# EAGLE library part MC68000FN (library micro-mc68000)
68xxx PROCESSOR
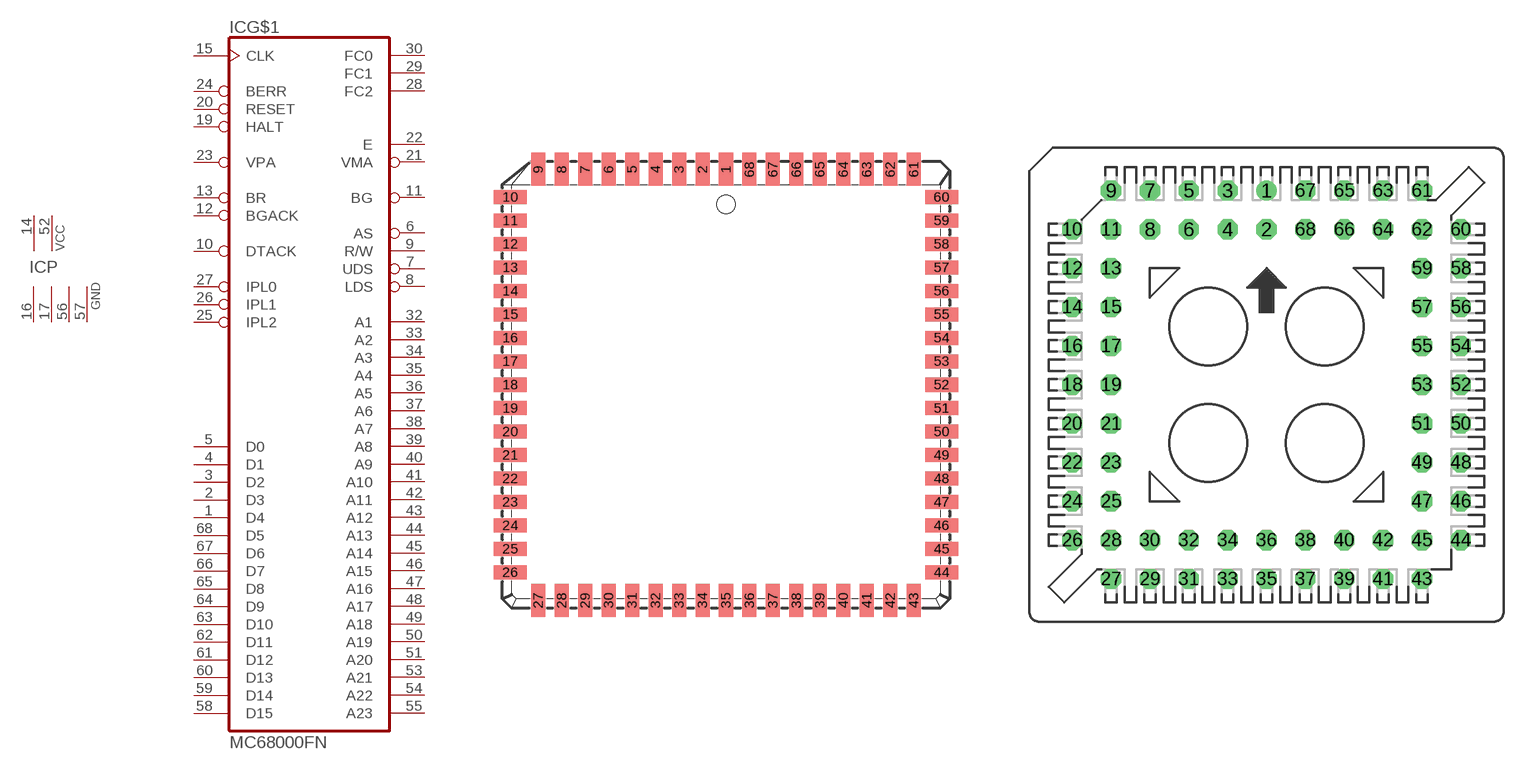
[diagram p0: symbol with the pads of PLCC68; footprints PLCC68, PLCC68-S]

Designator prefix IC; gates G$1=68000 P=2PWR4GND

## MC68000FN (MF: MOTOROLA; MPN: MC68HC000FN20; OC_FARNELL: unknown; OC_NEWARK: 66F833)  [PLCC68]
1  G$1:D4
2  G$1:D3
3  G$1:D2
4  G$1:D1
5  G$1:D0
6  G$1:AS  out
7  G$1:UDS  out
8  G$1:LDS  out
9  G$1:R/W  out
10  G$1:DTACK  in
11  G$1:BG  out
12  G$1:BGACK  in
13  G$1:BR  in
14  P:VCC  pwr
15  G$1:CLK  in
16  P:GND  pwr
17  P:GND  pwr
19  G$1:HALT
20  G$1:RESET
21  G$1:VMA  out
22  G$1:E  out
23  G$1:VPA  in
24  G$1:BERR  in
25  G$1:IPL2  in
26  G$1:IPL1  in
27  G$1:IPL0  in
28  G$1:FC2  out
29  G$1:FC1  out
30  G$1:FC0  out
32  G$1:A1  out
33  G$1:A2  out
34  G$1:A3  out
35  G$1:A4  out
36  G$1:A5  out
37  G$1:A6  out
38  G$1:A7  out
39  G$1:A8  out
40  G$1:A9  out
41  G$1:A10  out
42  G$1:A11  out
43  G$1:A12  out
44  G$1:A13  out
45  G$1:A14  out
46  G$1:A15  out
47  G$1:A16  out
48  G$1:A17  out
49  G$1:A18  out
50  G$1:A19  out
51  G$1:A20  out
52  P:VCC  pwr
53  G$1:A21  out
54  G$1:A22  out
55  G$1:A23  out
56  P:GND  pwr
57  P:GND  pwr
58  G$1:D15
59  G$1:D14
60  G$1:D13
61  G$1:D12
62  G$1:D11
63  G$1:D10
64  G$1:D9
65  G$1:D8
66  G$1:D7
67  G$1:D6
68  G$1:D5

## MC68000FN-SOC (OC_FARNELL: unknown; OC_NEWARK: unknown)  [PLCC68-S]
Pads as for PLCC68

## Footprint PLCC68 (pad centres in mm)
PLASTIC LEADED CHIP CARRIER square
smd 0.76 x 1.8: 1 0,11.67; 2 -1.27,11.67; 3 -2.54,11.67; 4 -3.81,11.67; 5 -5.08,11.67; 6 -6.35,11.67; 7 -7.62,11.67; 8 -8.89,11.67; 9 -10.16,11.67; 27 -10.16,-11.67; 28 -8.89,-11.67; 29 -7.62,-11.67; 30 -6.35,-11.67; 31 -5.08,-11.67; 32 -3.81,-11.67; 33 -2.54,-11.67; 34 -1.27,-11.67; 35 0,-11.67; 36 1.27,-11.67; 37 2.54,-11.67; 38 3.81,-11.67; 39 5.08,-11.67; 40 6.35,-11.67; 41 7.62,-11.67; 42 8.89,-11.67; 43 10.16,-11.67; 61 10.16,11.67; 62 8.89,11.67; 63 7.62,11.67; 64 6.35,11.67; 65 5.08,11.67; 66 3.81,11.67; 67 2.54,11.67; 68 1.27,11.67
smd 1.8 x 0.76: 10 -11.67,10.16; 11 -11.67,8.89; 12 -11.67,7.62; 13 -11.67,6.35; 14 -11.67,5.08; 15 -11.67,3.81; 16 -11.67,2.54; 17 -11.67,1.27; 18 -11.67,0; 19 -11.67,-1.27; 20 -11.67,-2.54; 21 -11.67,-3.81; 22 -11.67,-5.08; 23 -11.67,-6.35; 24 -11.67,-7.62; 25 -11.67,-8.89; 26 -11.67,-10.16; 44 11.67,-10.16; 45 11.67,-8.89; 46 11.67,-7.62; 47 11.67,-6.35; 48 11.67,-5.08; 49 11.67,-3.81; 50 11.67,-2.54; 51 11.67,-1.27; 52 11.67,0; 53 11.67,1.27; 54 11.67,2.54; 55 11.67,3.81; 56 11.67,5.08; 57 11.67,6.35; 58 11.67,7.62; 59 11.67,8.89; 60 11.67,10.16

## Footprint PLCC68-S (pad centres in mm)
PLCC Socked
drill 0.813 round: 1 0,12.7
drill 0.813 octagon: 2 0,10.16; 3 -2.54,12.7; 4 -2.54,10.16; 5 -5.08,12.7; 6 -5.08,10.16; 7 -7.62,12.7; 8 -7.62,10.16; 9 -10.16,12.7; 10 -12.7,10.16; 11 -10.16,10.16; 12 -12.7,7.62; 13 -10.16,7.62; 14 -12.7,5.08; 15 -10.16,5.08; 16 -12.7,2.54; 17 -10.16,2.54; 18 -12.7,0; 19 -10.16,0; 20 -12.7,-2.54; 21 -10.16,-2.54; 22 -12.7,-5.08; 23 -10.16,-5.08; 24 -12.7,-7.62; 25 -10.16,-7.62; 26 -12.7,-10.16; 27 -10.16,-12.7; 28 -10.16,-10.16; 29 -7.62,-12.7; 30 -7.62,-10.16; 31 -5.08,-12.7; 32 -5.08,-10.16; 33 -2.54,-12.7; 34 -2.54,-10.16; 35 0,-12.7; 36 0,-10.16; 37 2.54,-12.7; 38 2.54,-10.16; 39 5.08,-12.7; 40 5.08,-10.16; 41 7.62,-12.7; 42 7.62,-10.16; 43 10.16,-12.7; 44 12.7,-10.16; 45 10.16,-10.16; 46 12.7,-7.62; 47 10.16,-7.62; 48 12.7,-5.08; 49 10.16,-5.08; 50 12.7,-2.54; 51 10.16,-2.54; 52 12.7,0; 53 10.16,0; 54 12.7,2.54; 55 10.16,2.54; 56 12.7,5.08; 57 10.16,5.08; 58 12.7,7.62; 59 10.16,7.62; 60 12.7,10.16; 61 10.16,12.7; 62 10.16,10.16; 63 7.62,12.7; 64 7.62,10.16; 65 5.08,12.7; 66 5.08,10.16; 67 2.54,12.7; 68 2.54,10.16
